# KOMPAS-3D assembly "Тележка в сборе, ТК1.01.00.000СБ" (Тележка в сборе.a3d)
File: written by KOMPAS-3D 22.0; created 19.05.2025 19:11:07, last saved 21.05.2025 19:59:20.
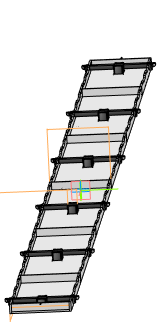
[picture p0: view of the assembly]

Document properties: Автор: user; Полное имя файла: ТК1.01.00.000 - Тележка в сборе.cdw

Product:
- Component [detail]: Ролик LFR5206-25-NPP  | qty 6  | pos. 9  | Масса: 0.442345; Раздел спецификации: Прочие изделия; source file: Ролик LFR5206-25-NPP.m3d
- Component [detail]: Ролик LFR5206-25-NPP  | qty 7  | Раздел спецификации: Прочие изделия; source file: Ролик LFR5206-25-NPP.m3d
- Component [assembly]: Корпус тележки  | designation ТК1.01.01.000СБ  | qty 1  | pos. 1  | Масса: 95.511296; Форматы листов документа: A4@4~3; source file: Корпус тележки\КД\ТК1.01.01.000 - Корпус тележки.spw, Корпус тележки\КД\ТК1.01.01.000 СБ - Корпус тележки.cdw, Корпус тележки\Корпус тележки.a3d
- Component [detail]: Ось  | designation ТК1.01.00.001  | qty 6  | pos. 2  | Материал: Сталь 40Х ГОСТ 4543-2016 (density 7850 kg/m3); Масса: 0.62382; Форматы листов документа: A4; source file: Ось.m3d, ТК1.01.00.001 - Ось.cdw
- Component [standard]: Шайба C 24 ГОСТ 10450-78  | qty 12  | pos. 6  | Масса: 0.020839; Раздел спецификации: Стандартные изделия; Рассекать на разрезах: no
- Component [standard]: Шайба A 12 ГОСТ 6958-78  | qty 12  | pos. 5  | Масса: 0.022195; Раздел спецификации: Стандартные изделия; Рассекать на разрезах: no
- Component [standard]: Шайба 12 ГОСТ 6402-70  | qty 12  | pos. 4  | Масса: 0.00345; Раздел спецификации: Стандартные изделия; Рассекать на разрезах: no; additional columns: 12
- Component [standard]: Винт с полукруглой головкой  | qty 12  | pos. 7  | Масса: 0.024928; Раздел спецификации: Стандартные изделия; Рассекать на разрезах: no; additional columns: Винт с полукруглой головкой и шестигранным углублением; ГОСТ ISO 7380-1; М12 x 30 - 08.8
- Component [standard]: Кольцо A25.50 ХГА.Ц9.хр ГОСТ 13942-86  | qty 12  | pos. 3  | Материал: Сталь 50 ХГА ГОСТ 14959-2016 (density 7850 kg/m3); Масса: 0.002684; Раздел спецификации: Стандартные изделия; Рассекать на разрезах: no
- Component [assembly]: Узел монтажный  | designation ТК1.03.00.000СБ  | qty 1  | pos. 10  | Форматы листов документа: A3; source file: ..\Узел монтажный\Узел монтажный _ ТК1.03.00.000 СБ.cdw, ..\Узел монтажный\Узел монтажный.a3d
- Component [detail]: Демпфер покупной  | qty 1  | pos. 3  | Масса: 0.356039; source file: ..\Упор отбойник.m3d
- Component [detail]: Демпфер покупной  | qty 1  | pos. 4  | Масса: 0.356039; source file: ..\Упор отбойник.m3d
- Part/product: Тележка в сборе  | designation ТК1.01.00.000СБ
    Масса: 103.447138
    Форматы листов документа: A3
    source file: ТК1.01.00.000 - Тележка в сборе.spw

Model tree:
1. Массив по сетке:1  (3 pattern instances)
     Шаг 1 = 854; Угол раствора = 90
2. Эскиз:1  (with: Скругление:2)
3. Линейный размер:1  (with: Элемент выдавливания:1)
     Значение = 166
4. Линейный размер:2  (with: Элемент выдавливания:1)
     Значение = 4470
5. Массив по сетке:3  (4 pattern instances)
     Шаг 1 = 854; Угол раствора = 90
6. Массив по сетке:4  (with: Элемент выдавливания:1)  (3 pattern instances)
     Шаг 1 = 854; Угол раствора = 90
7. Эскиз:2  (with: Элемент выдавливания:3, Элемент выдавливания:1, Элемент выдавливания:4)
8. Линейный размер:3  (with: Элемент выдавливания:2)
     Значение = 25.8
9. Массив по сетке:5  (with: Элемент выдавливания:1)  (6 pattern instances)
     Угол раствора = 90
10. Эскиз:3  (with: Элемент выдавливания:1, Элемент выдавливания:8, Элемент выдавливания:10)
11. Эскиз:4  (with: Элемент выдавливания:1)
12. Линейный размер:6  (with: Элемент выдавливания:1)
     Значение = 156
13. Эскиз:6  (with: Элемент выдавливания:1)
14. Эскиз:7  (with: Элемент выдавливания:1, Элемент выдавливания:3)
15. Элемент выдавливания:1  (with: Массив по сетке:1)  (6 pattern instances)
     Расстояние 2 = 10; Шаг 1 = 854; Угол раствора = 90; Шаг 2 = 10; Геометрический массив = 128
16. Эскиз:8  (with: Элемент выдавливания:1)
17. Элемент выдавливания:2  (with: Элемент выдавливания:1)
     Расстояние 2 = 8
18. Массив по сетке:2  (with: Элемент выдавливания:2, Элемент выдавливания:1, Элемент вращения:5, Отверстие:1, Элемент выдавливания:6)  (labels: Операция выдавливания:1)  (6 pattern instances)
     Шаг 1 = 854; Угол раствора = 90; Ориентация = 2; Ориентация = 2; Ориентация = 2; Ориентация = 2; Ориентация = 2; Ориентация = 2

Referenced files in D:\Работа\2025\5. Май\Задание №6 - Тележка для крыши\3Д\Тележка в сборе\: Ролик LFR5206-25-NPP.m3d, Ось.m3d, ТК1.01.00.001 - Ось.cdw
Referenced files in D:\Работа\2025\5. Май\Задание №6 - Тележка для крыши\3Д\Тележка в сборе\Корпус тележки\: Корпус тележки.a3d
Referenced files in D:\Работа\2025\5. Май\Задание №6 - Тележка для крыши\3Д\Тележка в сборе\Корпус тележки\КД\: ТК1.01.01.000 - Корпус тележки.spw, ТК1.01.01.000 СБ - Корпус тележки.cdw
Referenced files in D:\Работа\2025\5. Май\Задание №6 - Тележка для крыши\3Д\: Упор отбойник.m3d, Ролик LFR5206-25-NPP.m3d, Ось.m3d
Referenced files in D:\Работа\2025\5. Май\Задание №6 - Тележка для крыши\3Д\Узел монтажный\: Узел монтажный.a3d
Referenced files in C:\Program Files\ASCON\KOMPAS-3D v22\Libs\PolynomLib\DATA\vault\Methods\Kompas\3D\: PLib_Washer_1_712.m3d, PLib_Washer_2_712.m3d, PLib_Screw_ISO_7380_1500.m3d, PLib_Check_spring_rings_GOST_13942_911.m3d
Referenced files in D:\Program Files\ASCON\KOMPAS-3D v22\Libs\PolynomLib\DATA\vault\Methods\Kompas\3D\: PLib_Washer_1_712.m3d, PLib_Check_spring_rings_GOST_13942_911.m3d, PLib_Screw_ISO_7380_1500.m3d, PLib_Washer_2_712.m3d
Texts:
  ТК1.01.01.000
  ТК1.01.01.000 СБ
  ТК1.01.01.000       СБ
  ТК1.01.00.001
  BOSimple***Material:5b3b2396-5625-11d7-8827-00508b01a93a
  Крепежное изделие ГОСТ
  BOSimple***PART:51412fb7-6d63-7ba7-1d1b-63d03bb2bc0a***SHORTLOC:Root±140±10±10±60±20±20[Нет;Без покрытия;Без указания материала;-;24]
  BOSimple***PART:bdb4ee81-67e8-b5c4-1761-ea9b438f428c***SHORTLOC:Root±140±10±10±60±10±20[Нет;Без покрытия;Без указания материала;-;12]
  BOSimple***PART:7e278679-a80e-6205-d4ad-2f05a66bfd42***SHORTLOC:Root±140±10±30±110[Нет;Без покрытия;Без указания материала;12]
  Винт с полукруглой головкой и шестигранным углублением
  BOSimple***PART:22d0d234-c3fb-7cb5-7557-87eacf75c581***SHORTLOC:BD5A_871C2A98F8294977[1,75;30;12;Без покрытия;-;Не требуется покрытия;Без обработки;8.8;Steel]
  Ц9.хр
  BOSimple***PART:358777da-06df-04f2-faa3-d060e7cf20e1***SHORTLOC:B2AE_C71AD39EB7EB4E6E[25;A;9;Цинковое, хроматированное;2;Сталь 50 ХГА ГОСТ 14959-2016]
  Винт с полукруглой головкой и шестигранным углублением ГОСТ ISO 7380-1 -М12x30-08.8
  Точка начала. Х
  Точка начала. Y
  Точка начала. Z
  ТК1.01.00.000
  ТК1.01.00.000 СБ
  Ролик LFR5206-25-NPP (1)
  ТК1.01.01.000 Корпус тележки
  Ролик LFR5206-25-NPP (4)
  Ролик LFR5206-25-NPP (5)
  Ролик LFR5206-25-NPP (6)
  Ролик LFR5206-25-NPP (7)
  Ролик LFR5206-25-NPP (8)
  ТК1.01.00.001 Ось (1)
  Шайба C 24 ГОСТ 10450-78 (1)
  Шайба A 12 ГОСТ 6958-78 (1)
  Шайба 12 ГОСТ 6402-70 (1)
  Винт с полукруглой головкой (1)
  Кольцо A25.50 ХГА.Ц9.хр ГОСТ 13942-86 (1)
  Isp3
  Кольцо A25.50 ХГА.Ц9.хр ГОСТ 13942-86 (2)
  Винт с полукруглой головкой (2)
  Шайба 12 ГОСТ 6402-70 (2)
  Шайба A 12 ГОСТ 6958-78 (2)
  Шайба C 24 ГОСТ 10450-78 (2)
  Винт с полукруглой головкой (3)
  Шайба 12 ГОСТ 6402-70 (3)
  Демпфер покупной (1)
  Шайба A 12 ГОСТ 6958-78 (3)
  Демпфер покупной (2)
  Шайба C 24 ГОСТ 10450-78 (3)
  ТК1.01.00.001 Ось (2)
  Кольцо A25.50 ХГА.Ц9.хр ГОСТ 13942-86 (3)
  Ролик LFR5206-25-NPP (9)
  Кольцо A25.50 ХГА.Ц9.хр ГОСТ 13942-86 (4)
  Шайба A 12 ГОСТ 6958-78 (4)
  Шайба C 24 ГОСТ 10450-78 (4)
  Винт с полукруглой головкой (4)
  Шайба 12 ГОСТ 6402-70 (4)
  Винт с полукруглой головкой (5)
  Шайба 12 ГОСТ 6402-70 (5)
  Шайба A 12 ГОСТ 6958-78 (5)
  Шайба C 24 ГОСТ 10450-78 (5)
  ТК1.01.00.001 Ось (3)
  Кольцо A25.50 ХГА.Ц9.хр ГОСТ 13942-86 (5)
  Ролик LFR5206-25-NPP (10)
  Кольцо A25.50 ХГА.Ц9.хр ГОСТ 13942-86 (6)
  Шайба A 12 ГОСТ 6958-78 (6)
  Шайба C 24 ГОСТ 10450-78 (6)
  Винт с полукруглой головкой (6)
  Шайба 12 ГОСТ 6402-70 (6)
  Винт с полукруглой головкой (7)
  Шайба 12 ГОСТ 6402-70 (7)
  Шайба A 12 ГОСТ 6958-78 (7)
  Шайба C 24 ГОСТ 10450-78 (7)
  ТК1.01.00.001 Ось (4)
  Кольцо A25.50 ХГА.Ц9.хр ГОСТ 13942-86 (7)
  Ролик LFR5206-25-NPP (11)
  Кольцо A25.50 ХГА.Ц9.хр ГОСТ 13942-86 (8)
  Шайба A 12 ГОСТ 6958-78 (8)
  Шайба C 24 ГОСТ 10450-78 (8)
  Винт с полукруглой головкой (8)
  Шайба 12 ГОСТ 6402-70 (8)
  Винт с полукруглой головкой (9)
  Шайба 12 ГОСТ 6402-70 (9)
  Шайба A 12 ГОСТ 6958-78 (9)
  Шайба C 24 ГОСТ 10450-78 (9)
  ТК1.01.00.001 Ось (5)
  Кольцо A25.50 ХГА.Ц9.хр ГОСТ 13942-86 (9)
  Ролик LFR5206-25-NPP (12)
  Кольцо A25.50 ХГА.Ц9.хр ГОСТ 13942-86 (10)
  Шайба A 12 ГОСТ 6958-78 (10)
  Шайба C 24 ГОСТ 10450-78 (10)
  Винт с полукруглой головкой (10)
  Шайба 12 ГОСТ 6402-70 (10)
  Винт с полукруглой головкой (11)
  Шайба 12 ГОСТ 6402-70 (11)
  Шайба A 12 ГОСТ 6958-78 (11)
  Шайба C 24 ГОСТ 10450-78 (11)
  ТК1.01.00.001 Ось (6)
  Кольцо A25.50 ХГА.Ц9.хр ГОСТ 13942-86 (11)
  Ролик LFR5206-25-NPP (13)
  Кольцо A25.50 ХГА.Ц9.хр ГОСТ 13942-86 (12)
  Шайба A 12 ГОСТ 6958-78 (12)
  Шайба C 24 ГОСТ 10450-78 (12)
  Винт с полукруглой головкой (12)
  Шайба 12 ГОСТ 6402-70 (12)
  Cut of a button head
  Вырез на ширину l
